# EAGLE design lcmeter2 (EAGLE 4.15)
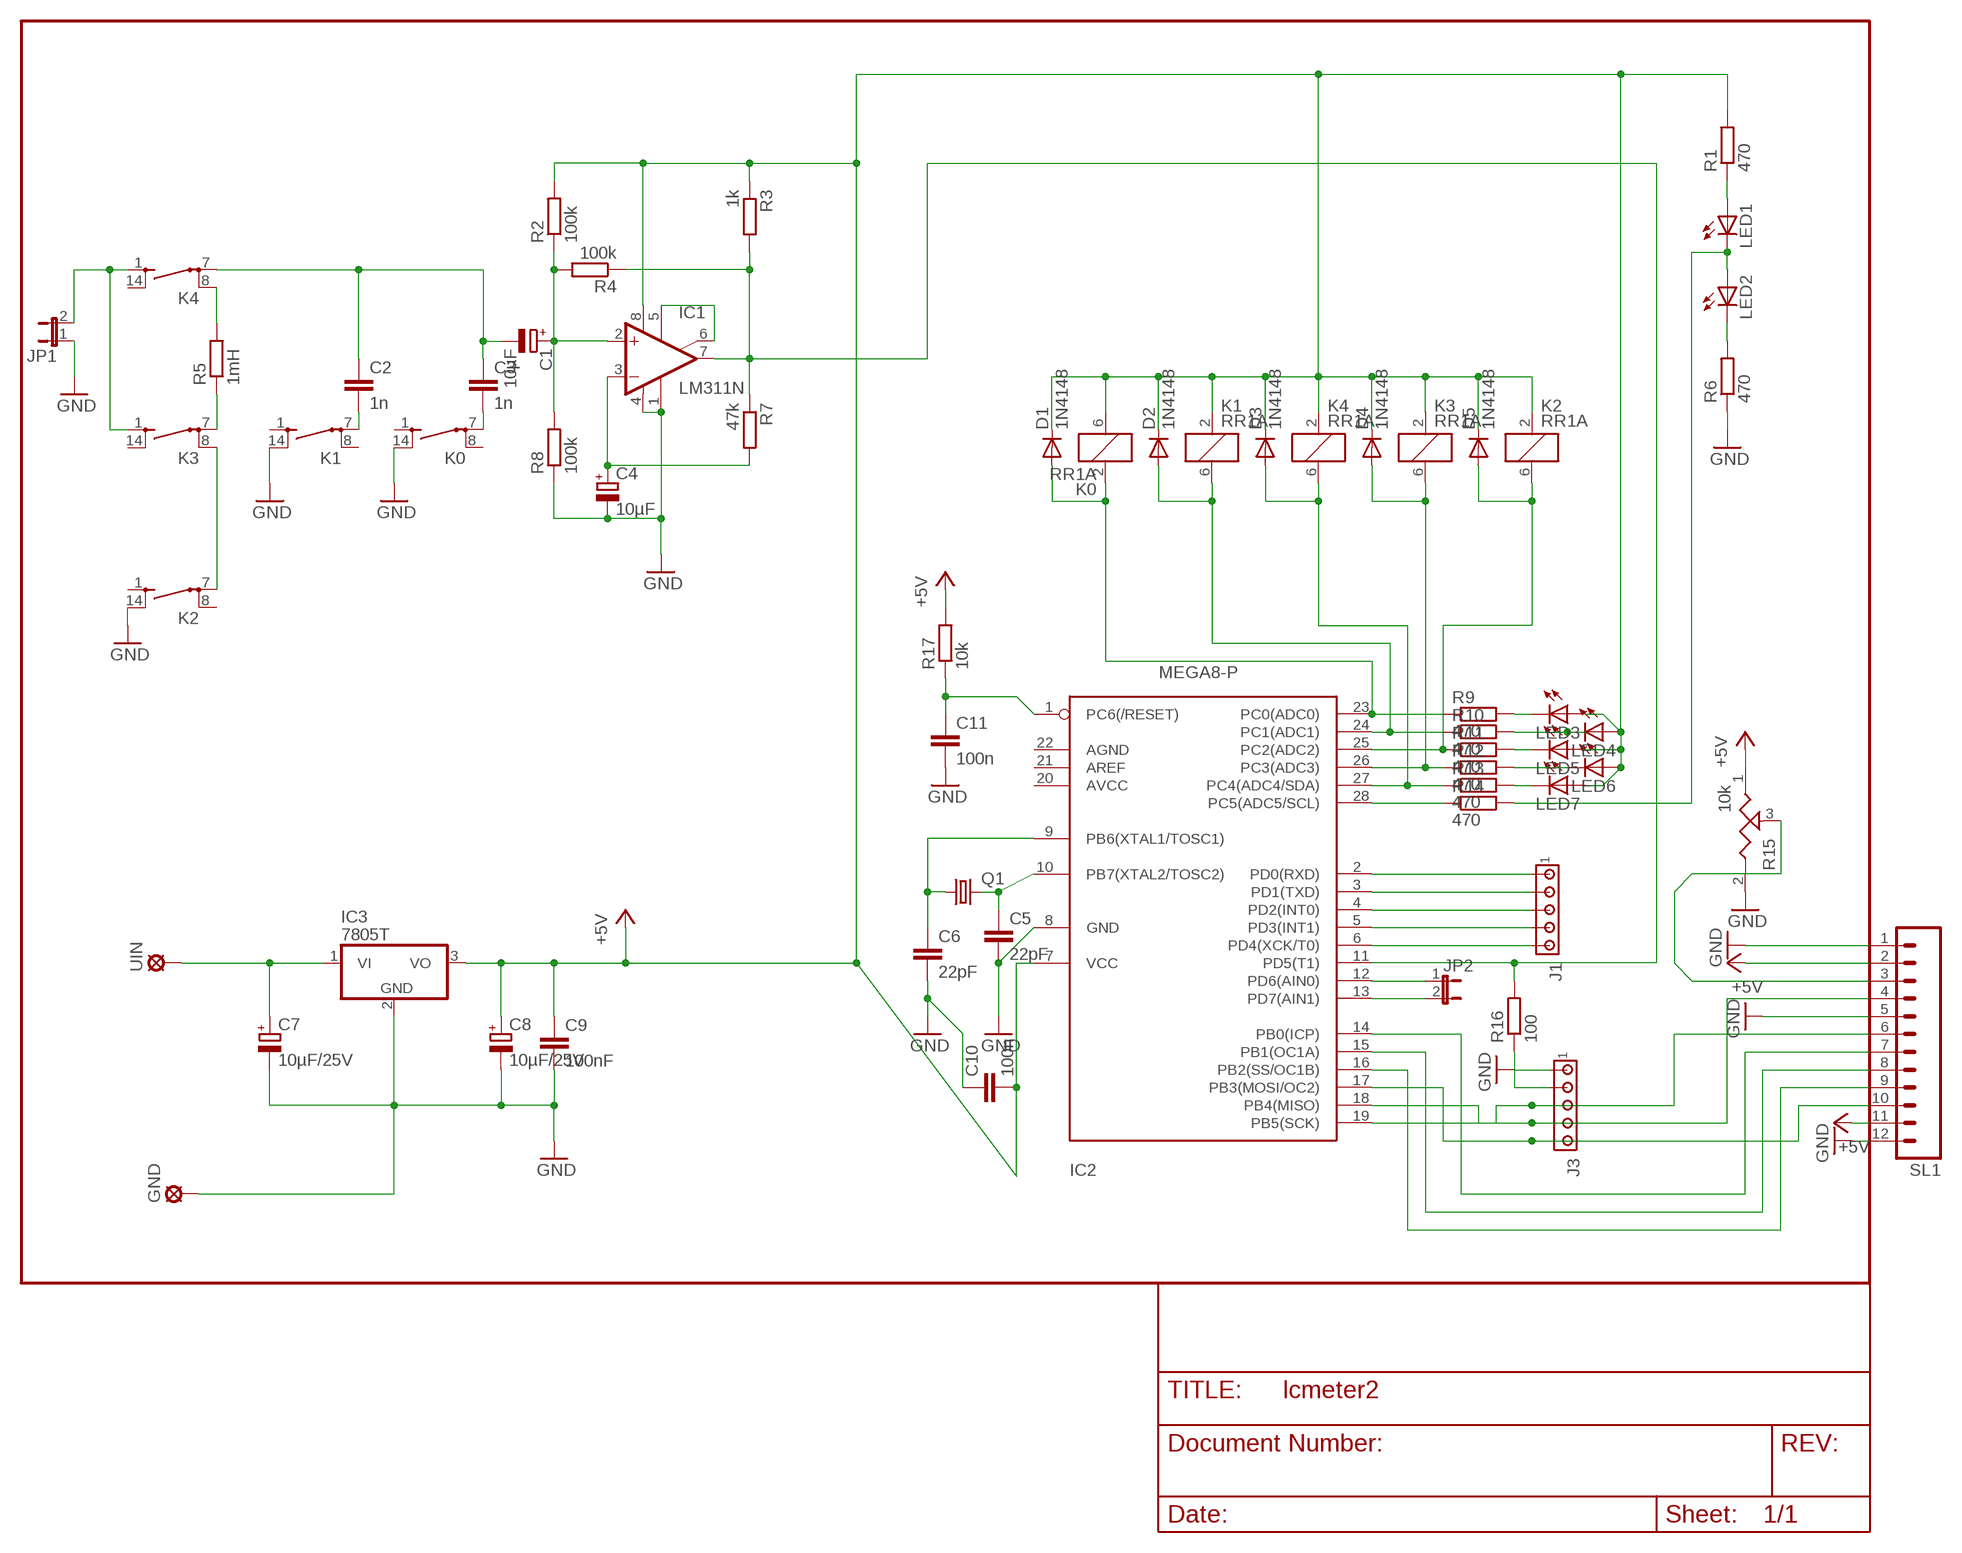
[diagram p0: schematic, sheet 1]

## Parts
C1  10µF  CPOL-EUE5-10.5  [E5-10,5]
C2  1n  C-EU025-030X050  [C025-030X050]
C3  1n  C-EU025-030X050  [C025-030X050]
C4  10µF  CPOL-EUE5-10.5  [E5-10,5]
C5  22pF  C-EU025-024X044  [C025-024X044]
C6  22pF  C-EU025-024X044  [C025-024X044]
C7  10µF/25V  CPOL-EUE2.5-5  [E2,5-5]
C8  10µF/25V  CPOL-EUE2.5-5  [E2,5-5]
C9  100nF  C-EU050-050X075  [C050-050X075]
C10  100n  C-EU025-030X050  [C025-030X050]
C11  100n  C-EU025-030X050  [C025-030X050]
D1  1N4148  [DO35-10]
D2  1N4148  [DO35-10]
D3  1N4148  [DO35-10]
D4  1N4148  [DO35-10]
D5  1N4148  [DO35-10]
GND  LSP10  [LSP10]
IC1  LM311N  [DIL08]
IC2  MEGA8-P  [DIL28-3]
IC3  7805T  [TO220H]
J1  MTA05-100  [10X05MTA]
J3  MTA05-100  [10X05MTA]
JP1  JP1E  [JP1]
JP2  JP1E  [JP1]
K0  RR1A  [RR1A]
K1  RR1A  [RR1A]
K2  RR1A  [RR1A]
K3  RR1A  [RR1A]
K4  RR1A  [RR1A]
LED1  LED5MM  [LED5MM]
LED2  LED5MM  [LED5MM]
LED3  LED5MM  [LED5MM]
LED4  LED5MM  [LED5MM]
LED5  LED5MM  [LED5MM]
LED6  LED5MM  [LED5MM]
LED7  LED5MM  [LED5MM]
Q1  CRYTALHC49U-V  [HC49U-V]
R1  470  R-EU_0309/12  [0309/12]
R2  100k  R-EU_0309/12  [0309/12]
R3  1k  R-EU_0309/12  [0309/12]
R4  100k  R-EU_0309/12  [0309/12]
R5  1mH  R-EU_0309/12  [0309/12]
R6  470  R-EU_0309/12  [0309/12]
R7  47k  R-EU_0309/12  [0309/12]
R8  100k  R-EU_0309/12  [0309/12]
R9  470  R-EU_0309/12  [0309/12]
R10  470  R-EU_0309/12  [0309/12]
R11  470  R-EU_0309/12  [0309/12]
R12  470  R-EU_0309/12  [0309/12]
R13  470  R-EU_0309/12  [0309/12]
R14  470  R-EU_0309/12  [0309/12]
R15  10k  POTUS-L  [PT-10]
R16  100  R-EU_0309/12  [0309/12]
R17  10k  R-EU_0309/12  [0309/12]
SL1  M12  [12P]
UIN  LSP10  [LSP10]

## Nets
+5V: C8.+ C9.1 C10.2 D1.C D2.C D3.C D4.C D5.C IC1.8(V+) IC2.7(VCC) IC3.3(VO) K0.6 K1.2 K2.2 K3.2 K4.2 LED3.A LED4.A LED5.A LED6.A LED7.A R1.2 R2.2 R3.1 R15.1 R17.2 SL1.2 SL1.11
GND: C4.- C5.2 C6.2 C7.- C8.- C9.2 C10.1 C11.2 GND.MP IC1.1(GND) IC1.4(V-) IC2.8(GND) IC3.2(GND) J3.1 JP1.1 K0.14(2:S) K1.14(2:S) K2.14(2:S) R6.1 R8.1 R15.2 SL1.1 SL1.5 SL1.12
N$3: D4.A IC2.26(PC3(ADC3)) K3.6 R12.1
N$4: C1.- C2.1 C3.1 K4.7(2:P)
N$5: LED2.K(C) R6.2
N$6: IC2.28(PC5(ADC5/SCL)) R14.1
N$7: LED3.K(C) R9.2
N$8: LED4.K(C) R10.2
N$9: LED1.K(C) LED2.A R14.2
N$10: C1.+ IC1.2(+IN) R2.1 R4.2 R8.2
N$11: C7.+ IC3.1(VI) UIN.MP
N$12: JP1.2 K3.1(2:S) K4.1(2:S)
N$14: K4.8(2:P) R5.2
N$15: C4.+ IC1.3(-IN) R7.2
N$16: K3.7(2:P) R5.1
N$17: IC1.5(ON) IC1.6(ON/STR)
N$18: IC1.7(OUT) IC2.11(PD5(T1)) R3.2 R4.1 R7.1 R16.2
N$20: C3.2 K0.7(2:P)
N$21: C2.2 K1.7(2:P)
N$22: C5.1 IC2.10(PB7(XTAL2/TOSC2)) Q1.2
N$23: LED5.K(C) R11.2
N$24: C6.1 IC2.9(PB6(XTAL1/TOSC1)) Q1.1
N$25: LED6.K(C) R12.2
N$26: LED7.K(C) R13.2
N$28: D1.A IC2.23(PC0(ADC0)) K0.2 R9.1
N$29: LED1.A R1.1
N$30: C11.1 IC2.1(PC6(/RESET)) R17.1
N$32: R15.3 SL1.3
N$36: J3.2 R16.1
N$37: IC2.14(PB0(ICP)) SL1.7
N$38: IC2.15(PB1(OC1A)) SL1.8
N$39: D3.A IC2.27(PC4(ADC4/SDA)) K4.6 R13.1
N$40: IC2.2(PD0(RXD)) J1.1
N$41: IC2.3(PD1(TXD)) J1.2
N$42: IC2.4(PD2(INT0)) J1.3
N$43: IC2.5(PD3(INT1)) J1.4
N$44: IC2.6(PD4(XCK/T0)) J1.5
N$45: IC2.12(PD6(AIN0)) JP2.1
N$46: IC2.13(PD7(AIN1)) JP2.2
N$49: IC2.18(PB4(MISO)) J3.4 SL1.4
N$50: IC2.17(PB3(MOSI/OC2)) J3.5 SL1.10
N$53: IC2.19(PB5(SCK)) J3.3 SL1.6
N$54: IC2.16(PB2(SS/OC1B)) SL1.9
N$55: D2.A IC2.24(PC1(ADC1)) K1.6 R10.1
N$58: D5.A IC2.25(PC2(ADC2)) K2.6 R11.1
N$62: K2.7(2:P) K3.8(2:P)
Unconnected: IC2.20(AVCC) IC2.21(AREF) IC2.22(AGND) K0.1(2:S) K0.8(2:P) K1.1(2:S) K1.8(2:P) K2.1(2:S) K2.8(2:P) K3.14(2:S) K4.14(2:S)

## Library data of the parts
C1 C4 C7 C8 = rcl:CPOL-EU: POLARIZED CAPACITOR, European symbol
C2 C3 C5 C6 C9-C11 = rcl:C-EU: CAPACITOR, European symbol
D1-D5 = diode:1N4148: DIODE
GND UIN = solpad:LSP10: SOLDER PAD
IC1 = linear:LM311: COMPARATOR
IC2 = avr:MEGA8-P: MICROCONTROLLER 8 Kbytes FLASH 1 kbytes SRAM 512 bytes EEPROM USART 4-channel 10 bit ADC 2-channel 8 bit ADC
IC3 = linear:78*: Positive VOLTAGE REGULATOR Source: http://cache.national.com/ds/LM/LM78L05.pdf http://www.fairchildsemi.com/ds/LM/LM7805.pdf
J1 J3 = con-amp:MTA05-100: AMP connector
JP1 JP2 = jumper:JP1E: JUMPER
K0 K1-K4 = relay:RR1A: RELAY reed, polarity, 1 x norm. open with shield
LED1-LED7 = led:LED: LED
Q1 = crystal:CRYTAL: CRYSTAL
R1-R14 R16 R17 = rcl:R-EU_: RESISTOR, European symbol
R15 = discrete:POTUS-L
SL1 = con-amp-quick:M12: AMP QUICK CONNECTOR

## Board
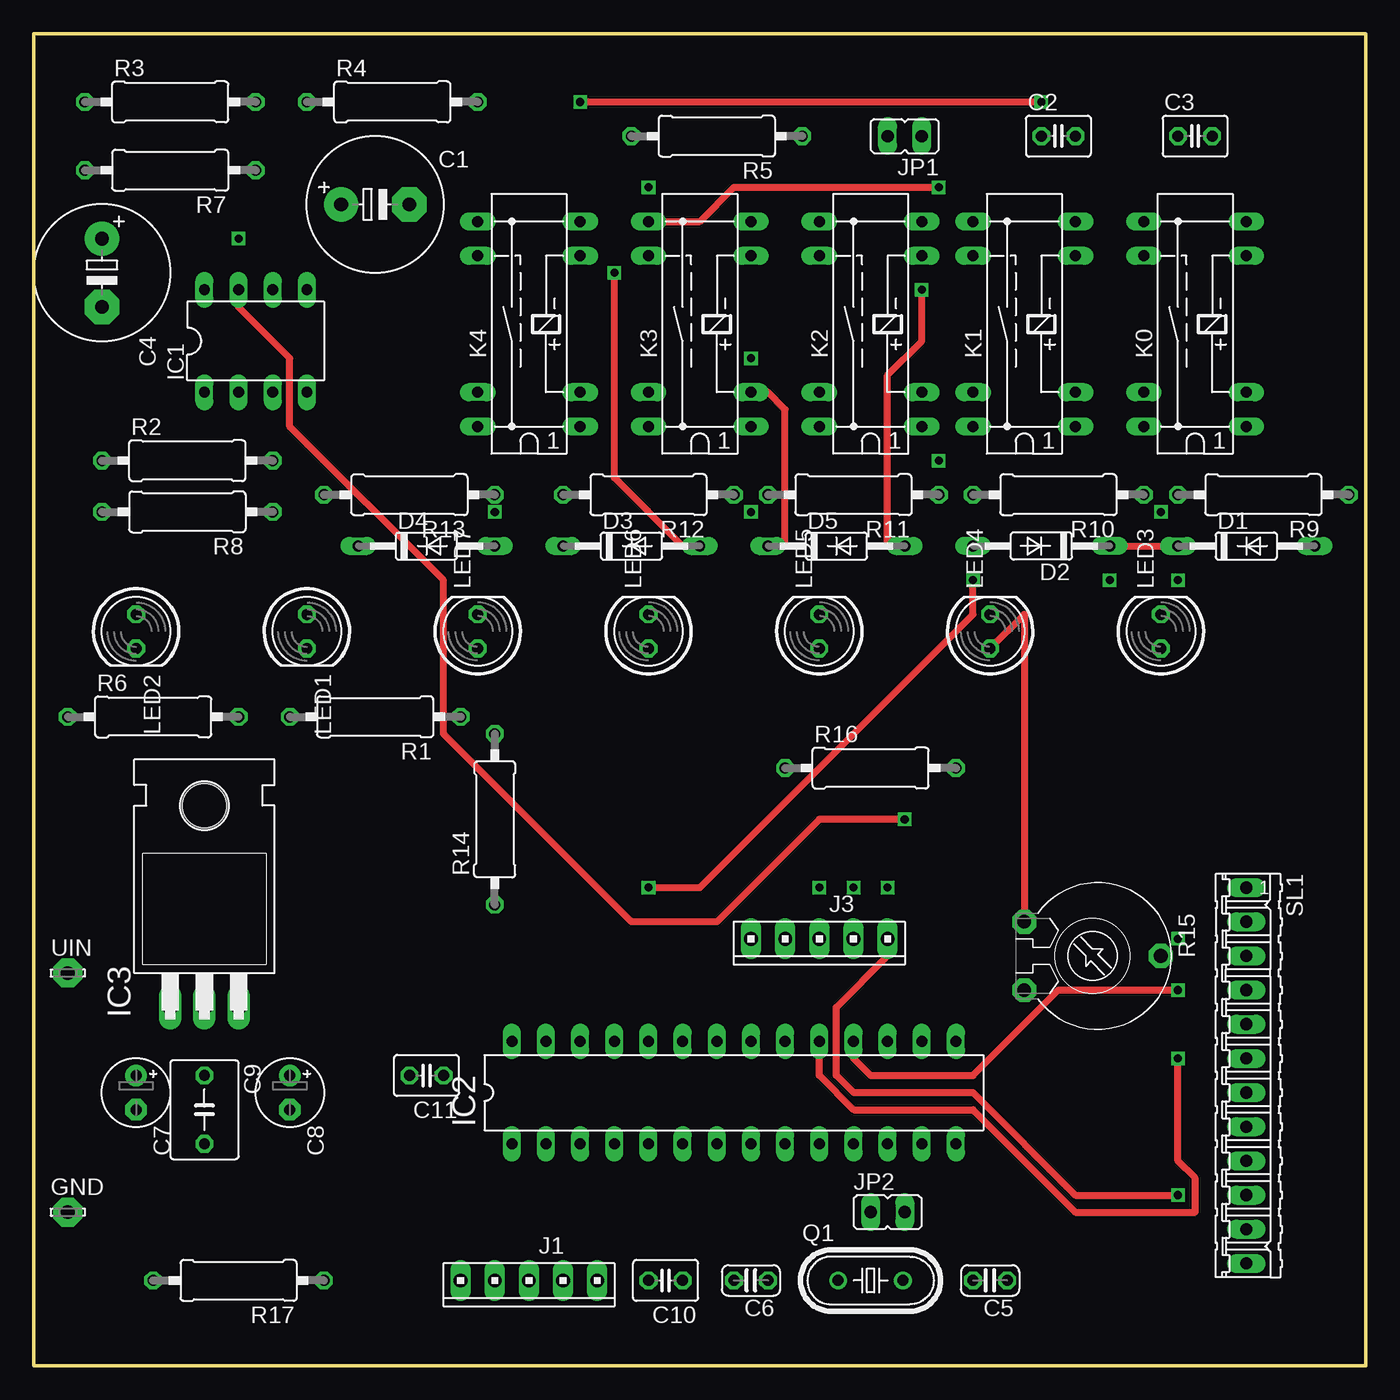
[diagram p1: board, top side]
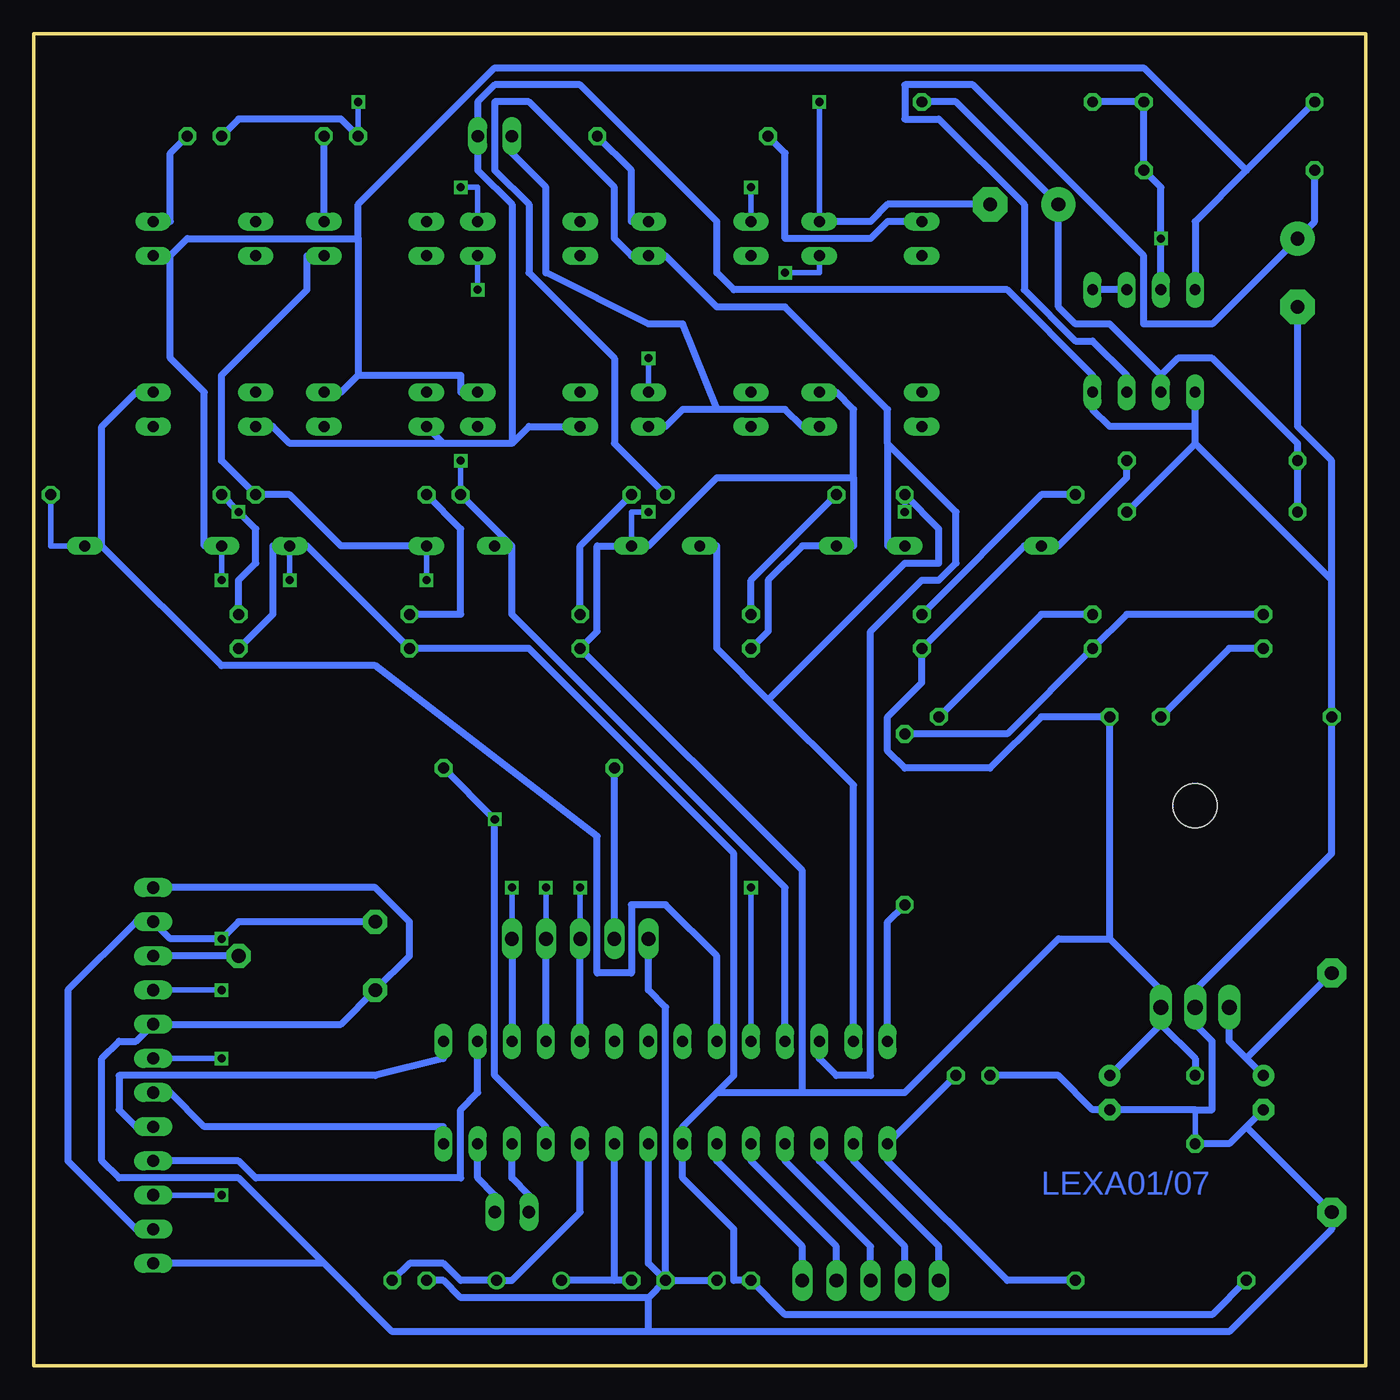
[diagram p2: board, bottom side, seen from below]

Size 99.06 x 99.06 mm. Coordinates in mm from the lower left corner, seen from the top.
Outline: 0,99.06 99.06,99.06 99.06,0 0,0 0,99.06
Copper layers (1*16): Top 0.035mm / dielectric 1.5mm / Bottom 0.035mm
Design rules "default": minimum track width 20mil, minimum drill 24mil, track to track 8mil, track to pad 8mil, pad to pad 8mil, via to via 8mil, smd to smd 8mil, copper to edge 40mil, drill to drill 8mil, minimum pad ring 10mil, minimum via ring 8mil, stop-mask expansion 4mil, vias tented up to drill 0mil, thermal gap 10mil

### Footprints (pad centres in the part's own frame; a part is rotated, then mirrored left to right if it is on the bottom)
E5-10,5 = drill 1.016 pad 2.54 round: + -2.54,0 | drill 1.016 pad 2.54 octagon: - 2.54,0
C025-030X050 = drill 0.813 octagon: 1 -1.27,0; 2 1.27,0
C025-024X044 = drill 0.813 octagon: 1 -1.27,0; 2 1.27,0
E2,5-5 = drill 0.813 pad 1.6 round: + -1.27,0 | drill 0.813 pad 1.6 octagon: - 1.27,0
C050-050X075 = drill 0.813 octagon: 1 -2.54,0; 2 2.54,0
DO35-10 = drill 0.813 long: A 5.08,0; C -5.08,0
LSP10 = drill 1.016 pad 2.159 octagon: MP 0,0
DIL08 = drill 0.813 long: 1 -3.81,-3.81; 2 -1.27,-3.81; 3 1.27,-3.81; 4 3.81,-3.81; 5 3.81,3.81; 6 1.27,3.81; 7 -1.27,3.81; 8 -3.81,3.81
DIL28-3 = drill 0.813 long: 1 -16.51,-3.81; 2 -13.97,-3.81; 3 -11.43,-3.81; 4 -8.89,-3.81; 5 -6.35,-3.81; 6 -3.81,-3.81; 7 -1.27,-3.81; 8 1.27,-3.81; 9 3.81,-3.81; 10 6.35,-3.81; 11 8.89,-3.81; 12 11.43,-3.81; 13 13.97,-3.81; 14 16.51,-3.81; 15 16.51,3.81; 16 13.97,3.81; 17 11.43,3.81; 18 8.89,3.81; 19 6.35,3.81; 20 3.81,3.81; 21 1.27,3.81; 22 -1.27,3.81; 23 -3.81,3.81; 24 -6.35,3.81; 25 -8.89,3.81; 26 -11.43,3.81; 27 -13.97,3.81; 28 -16.51,3.81
TO220H = drill 1.118 long: 1 -2.54,-10.16; 2 0,-10.16; 3 2.54,-10.16 | hole 3.302: 0,4.826
10X05MTA = drill 1.016 long: 1 5.08,0; 2 2.54,0; 3 0,0; 4 -2.54,0; 5 -5.08,0
JP1 = drill 0.914 long: 1 0,-1.27; 2 0,1.27
RR1A = drill 0.813 long: 1 -7.62,-3.81; 2 -5.08,-3.81; 6 5.08,-3.81; 7 7.62,-3.81; 8 7.62,3.81; 9 5.08,3.81; 13 -5.08,3.81; 14 -7.62,3.81
LED5MM = drill 0.813 octagon: A -1.27,0; K 1.27,0
HC49U-V = drill 0.813 round: 1 -2.413,0; 2 2.413,0
0309/12 = drill 0.813 octagon: 1 -6.35,0; 2 6.35,0
PT-10 = drill 1.016 pad 1.778 octagon: 1 -2.54,-5.08; 2 2.54,-5.08; 3 0,5.08
12P = drill 0.914 long: 1 -13.97,0; 2 -11.43,0; 3 -8.89,0; 4 -6.35,0; 5 -3.81,0; 6 -1.27,0; 7 1.27,0; 8 3.81,0; 9 6.35,0; 10 8.89,0; 11 11.43,0; 12 13.97,0

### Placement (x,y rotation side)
C1  25.4,86.36 0 top
C2  76.2,91.44 0 top
C3  86.36,91.44 0 top
C4  5.08,81.28 270 top
C5  71.12,6.35 180 top
C6  53.34,6.35 180 top
C7  7.62,20.32 270 top
C8  19.05,20.32 270 top
C9  12.7,19.05 270 top
C10  46.99,6.35 180 top
C11  29.21,21.59 180 top
D1  90.17,60.96 0 top
D2  74.93,60.96 180 top
D3  44.45,60.96 0 top
D4  29.21,60.96 0 top
D5  59.69,60.96 0 top
GND  2.54,11.43 0 top
IC1  16.51,76.2 0 top
IC2  52.07,20.32 0 top
IC3  12.7,36.83 0 top
J1  36.83,6.35 180 top
J3  58.42,31.75 180 top
JP1  64.77,91.44 90 top
JP2  63.5,11.43 270 top
K0  86.36,77.47 90 top
K1  73.66,77.47 90 top
K2  62.23,77.47 90 top
K3  49.53,77.47 90 top
K4  36.83,77.47 90 top
LED1  20.32,54.61 270 top
LED2  7.62,54.61 270 top
LED3  83.82,54.61 90 top
LED4  71.12,54.61 90 top
LED5  58.42,54.61 90 top
LED6  45.72,54.61 90 top
LED7  33.02,54.61 90 top
Q1  62.23,6.35 0 top
R1  25.4,48.26 180 top
R2  11.43,67.31 0 top
R3  10.16,93.98 0 top
R4  26.67,93.98 0 top
R5  50.8,91.44 180 top
R6  8.89,48.26 0 top
R7  10.16,88.9 180 top
R8  11.43,63.5 180 top
R9  91.44,64.77 180 top
R10  76.2,64.77 180 top
R11  60.96,64.77 180 top
R12  45.72,64.77 180 top
R13  27.94,64.77 180 top
R14  34.29,40.64 90 top
R15  78.74,30.48 270 top
R16  62.23,44.45 0 top
R17  15.24,6.35 180 top
SL1  90.17,21.59 270 top
UIN  2.54,29.21 0 top

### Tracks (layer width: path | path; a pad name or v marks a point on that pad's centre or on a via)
+5V  (via drill 0.6)
  Top 0.508: D3.C 40.64,60.96 | LED4.A 73.66,55.88 R15.1 | 78.74,60.96 D2.C D1.C | IC3.3 15.24,25.4 | K3.2 54.61,72.39 55.88,71.12 55.88,60.96 D5.C
  Bottom 0.406: D2.C v80.01,58.42 | D1.C v85.09,58.42 | K3.2 v53.34,74.93 | v53.34,63.5 54.61,63.5 D5.C
  Bottom 0.508: R17.2 11.43,3.81 43.18,3.81 C10.2 46.99,6.35 46.99,10.16 50.8,13.97 IC2.7 50.8,17.78 48.26,20.32 | C9.1 12.7,22.86 15.24,25.4 | 19.05,31.75 R1.2 24.13,48.26 27.94,44.45 34.29,44.45 35.56,45.72 35.56,48.26 33.02,50.8 LED7.A 25.4,60.96 D4.C 22.86,60.96 17.78,66.04 R2.2 | 19.05,31.75 15.24,27.94 IC3.3 15.24,25.4 | 15.24,25.4 C8.+ | LED6.A 44.45,54.61 44.45,58.42 41.91,60.96 D3.C 38.1,60.96 38.1,66.04 | SL1.11 91.44,10.16 96.52,15.24 96.52,27.94 91.44,33.02 SL1.2 88.9,31.75 v85.09,31.75 83.82,33.02 R15.1 | 38.1,66.04 38.1,71.12 39.37,72.39 K4.2 | 38.1,66.04 48.26,66.04 53.34,60.96 D5.C 57.15,60.96 57.15,54.61 LED5.A 41.91,36.83 41.91,20.32 | LED3.A 81.28,55.88 81.28,60.96 D2.C 78.74,60.96 LED4.A 62.23,53.34 46.99,38.1 46.99,21.59 48.26,20.32 | 19.05,31.75 22.86,31.75 34.29,20.32 41.91,20.32 | 48.26,20.32 41.91,20.32 | 8.89,88.9 R3.1 | 8.89,88.9 12.7,85.09 IC1.8 | 74.93,73.66 67.31,73.66 67.31,72.39 K2.2 | 74.93,73.66 76.2,72.39 K1.2 | 88.9,82.55 88.9,74.93 86.36,72.39 86.36,60.96 D1.C | 74.93,83.82 74.93,73.66 | 74.93,83.82 87.63,83.82 88.9,82.55 | 88.9,82.55 K0.6 | 8.89,88.9 16.51,96.52 64.77,96.52 74.93,86.36 74.93,83.82
GND
  Bottom 0.406: C9.2 12.7,19.05
  Bottom 0.508: SL1.1 73.66,35.56 71.12,33.02 71.12,30.48 R15.2 76.2,25.4 SL1.5 91.44,24.13 92.71,24.13 93.98,22.86 93.98,15.24 92.71,13.97 83.82,13.97 77.47,7.62 | C6.2 C10.1 | C6.2 53.34,7.62 IC2.8 | C5.2 68.58,6.35 67.31,5.08 53.34,5.08 | 53.34,5.08 C6.2 | J3.1 53.34,27.94 52.07,26.67 C6.2 | 63.5,68.58 62.23,69.85 K2.14 | 63.5,68.58 68.58,68.58 | 68.58,68.58 K1.14 | 68.58,68.58 80.01,68.58 81.28,69.85 K0.14 | 63.5,68.58 63.5,86.36 66.04,88.9 JP1.1 66.04,93.98 64.77,95.25 58.42,95.25 48.26,85.09 48.26,81.28 46.99,80.01 26.67,80.01 20.32,73.66 IC1.4 20.32,71.12 19.05,69.85 12.7,69.85 | C11.2 22.86,21.59 20.32,19.05 C8.- 12.7,19.05 11.43,19.05 11.43,24.13 12.7,25.4 IC3.2 12.7,27.94 2.54,38.1 R6.1 2.54,58.42 | C9.2 10.16,16.51 8.89,17.78 | 8.89,17.78 C7.- | 8.89,17.78 GND.MP 2.54,10.16 10.16,2.54 53.34,2.54 | 12.7,68.58 12.7,69.85 | 12.7,68.58 R8.1 | 12.7,69.85 IC1.1 | C4.- 5.08,69.85 2.54,67.31 2.54,58.42 | 2.54,58.42 12.7,68.58 | 77.47,7.62 72.39,2.54 53.34,2.54 | 53.34,2.54 53.34,5.08 | 77.47,7.62 SL1.12
N$3
  Bottom 0.508: 35.56,68.58 35.56,60.96 D4.A | 35.56,68.58 35.56,71.12 43.18,78.74 48.26,78.74 52.07,82.55 K3.6 54.61,82.55 55.88,83.82 55.88,87.63 62.23,93.98 64.77,93.98 64.77,88.9 62.23,86.36 62.23,81.28 55.88,74.93 55.88,68.58 R12.1 | 35.56,68.58 30.48,63.5 30.48,59.69 31.75,58.42 33.02,58.42 36.83,54.61 36.83,21.59 39.37,21.59 40.64,22.86 IC2.26
N$4  (via drill 0.6)
  Top 0.508: v40.64,93.98 v74.93,93.98
  Bottom 0.406: K4.7 v40.64,93.98 | v74.93,93.98 C2.1
  Bottom 0.508: C1.- 35.56,86.36 36.83,85.09 K4.7 | C2.1 76.2,92.71 83.82,92.71 C3.1
N$5
  Bottom 0.508: LED2.K 10.16,53.34 R6.2
N$6
  Bottom 0.508: R14.1 35.56,33.02 IC2.28
N$7  (via drill 0.6)
  Bottom 0.508: LED3.K 83.82,58.42 82.55,59.69 82.55,62.23 v83.82,63.5 R9.2
N$8
  Bottom 0.508: R10.2 67.31,62.23 67.31,55.88 LED4.K
N$9
  Bottom 0.508: LED2.A 17.78,55.88 LED1.K 26.67,46.99 R14.2
N$10
  Bottom 0.508: R8.2 R2.1 5.08,68.58 11.43,74.93 13.97,74.93 15.24,73.66 | R4.2 30.48,93.98 C1.+ 22.86,78.74 21.59,77.47 19.05,77.47 15.24,73.66 | 15.24,73.66 IC1.2
N$11
  Bottom 0.508: 8.89,22.86 10.16,24.13 IC3.1 | C7.+ 8.89,22.86 | 8.89,22.86 UIN.MP
N$12
  Bottom 0.508: 48.26,71.12 50.8,71.12 52.07,69.85 K3.1 | 48.26,71.12 43.18,71.12 41.91,69.85 K4.1 | 48.26,71.12 50.8,77.47 53.34,77.47 60.96,81.28 60.96,87.63 63.5,90.17 JP1.2
N$14
  Bottom 0.508: R5.2 43.18,90.17 43.18,83.82 36.83,83.82 35.56,85.09 K4.8
N$15
  Bottom 0.508: IC1.3 17.78,73.66 20.32,76.2 21.59,76.2 25.4,80.01 25.4,86.36 31.75,92.71 34.29,92.71 34.29,95.25 29.21,95.25 16.51,82.55 16.51,77.47 11.43,77.47 C4.+ 3.81,85.09 R7.2
N$16
  Bottom 0.508: R5.1 54.61,88.9 54.61,85.09 K3.7
N$17
  Bottom 0.508: IC1.6 IC1.5
N$18  (via drill 0.6)
  Top 0.508: v64.77,40.64 58.42,40.64 50.8,33.02 44.45,33.02 30.48,46.99 30.48,58.42 19.05,69.85 19.05,74.93 15.24,78.74 IC1.7
  Bottom 0.508: R16.2 v64.77,40.64 64.77,21.59 60.96,17.78 IC2.11 | R4.1 R3.2 R7.1 15.24,87.63 v15.24,83.82 IC1.7
N$20
  Bottom 0.508: C3.2 88.9,90.17 88.9,85.09 K0.7
N$21
  Bottom 0.508: K1.7 C2.2
N$22
  Bottom 0.508: C5.1 71.12,7.62 68.58,7.62 67.31,6.35 Q1.2 63.5,6.35 58.42,11.43 IC2.10
N$23
  Bottom 0.508: R11.2 58.42,60.96 LED5.K
N$24
  Bottom 0.508: C6.1 55.88,6.35 | 55.88,6.35 Q1.1 | 55.88,6.35 IC2.9
N$25
  Bottom 0.508: R12.2 45.72,58.42 LED6.K
N$26
  Bottom 0.508: R13.2 24.13,64.77 LED7.K
N$28
  Bottom 0.406: R9.1 97.79,60.96 D1.A
  Bottom 0.508: 93.98,60.96 85.09,52.07 73.66,52.07 57.15,39.37 57.15,29.21 54.61,29.21 54.61,34.29 52.07,34.29 48.26,30.48 IC2.23 | 93.98,60.96 93.98,69.85 91.44,72.39 K0.2 | 93.98,60.96 D1.A
N$29
  Bottom 0.508: LED1.A 24.13,55.88 R1.1
N$30
  Bottom 0.508: R17.1 26.67,6.35 35.56,15.24 IC2.1 C11.1
N$32
  Bottom 0.508: R15.3 SL1.3
N$36
  Bottom 0.508: J3.2 R16.1
N$37
  Bottom 0.508: IC2.14 68.58,17.78 86.36,17.78 88.9,20.32 SL1.7
N$38
  Bottom 0.508: IC2.15 68.58,22.86 73.66,21.59 92.71,21.59 92.71,19.05 91.44,17.78 SL1.8
N$39  (via drill 0.6)
  Top 0.508: v43.18,81.28 43.18,66.04 48.26,60.96 D3.A
  Bottom 0.406: R13.1 v34.29,63.5 | K4.6 40.64,81.28 v43.18,81.28
  Bottom 0.508: 44.45,49.53 38.1,43.18 IC2.27 | 44.45,49.53 48.26,53.34 48.26,60.96 D3.A | R13.1 31.75,62.23 31.75,59.69 34.29,59.69 44.45,49.53
N$40
  Bottom 0.508: IC2.2 38.1,15.24 31.75,8.89 J1.1
N$41
  Bottom 0.508: IC2.3 40.64,15.24 34.29,8.89 J1.2
N$42
  Bottom 0.508: IC2.4 43.18,15.24 36.83,8.89 J1.3
N$43
  Bottom 0.508: IC2.5 45.72,15.24 39.37,8.89 J1.4
N$44
  Bottom 0.508: IC2.6 48.26,15.24 41.91,8.89 J1.5
N$45
  Bottom 0.508: IC2.12 63.5,13.97 62.23,12.7 JP2.1
N$46
  Bottom 0.508: IC2.13 66.04,13.97 64.77,12.7 JP2.2
N$49  (via drill 0.6)
  Top 0.508: v85.09,27.94 76.2,27.94 69.85,21.59 62.23,21.59 60.96,22.86 IC2.18
  Bottom 0.406: J3.4 v60.96,35.56 | v85.09,27.94 SL1.4
  Bottom 0.508: IC2.18 J3.4
N$50  (via drill 0.6)
  Top 0.508: v85.09,12.7 77.47,12.7 69.85,20.32 60.96,20.32 59.69,21.59 59.69,26.67 63.5,30.48 J3.5
  Bottom 0.406: J3.5 v63.5,35.56 | v85.09,12.7 SL1.10
  Bottom 0.508: J3.5 IC2.17
N$53  (via drill 0.6)
  Top 0.508: v85.09,22.86 85.09,15.24 86.36,13.97 86.36,11.43 77.47,11.43 69.85,19.05 60.96,19.05 58.42,21.59 IC2.19
  Bottom 0.406: J3.3 v58.42,35.56 | v85.09,22.86 SL1.6
  Bottom 0.508: IC2.19 J3.3
N$54
  Bottom 0.508: IC2.16 66.04,20.32 67.31,19.05 67.31,13.97 82.55,13.97 83.82,15.24 SL1.9
N$55  (via drill 0.6)
  Top 0.508: v45.72,35.56 49.53,35.56 69.85,55.88 v69.85,58.42
  Bottom 0.406: IC2.24 v45.72,35.56 | v69.85,58.42 D2.A
  Bottom 0.508: D2.A 76.2,60.96 80.01,64.77 R10.1 85.09,67.31 85.09,73.66 78.74,80.01 78.74,82.55 K1.6
N$58  (via drill 0.6)
  Top 0.508: v66.04,80.01 66.04,76.2 63.5,73.66 63.5,60.96 D5.A
  Bottom 0.406: v66.04,80.01 K2.6 | R11.1 v67.31,67.31
  Bottom 0.508: 63.5,60.96 63.5,55.88 43.18,35.56 IC2.25 | 63.5,60.96 R11.1 | 63.5,60.96 D5.A
N$62  (via drill 0.6)
  Top 0.508: v67.31,87.63 52.07,87.63 49.53,85.09 K3.8
  Bottom 0.406: K3.8 v45.72,87.63 | v67.31,87.63 66.04,87.63 K2.7

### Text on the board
Bottom: LEXA01/07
